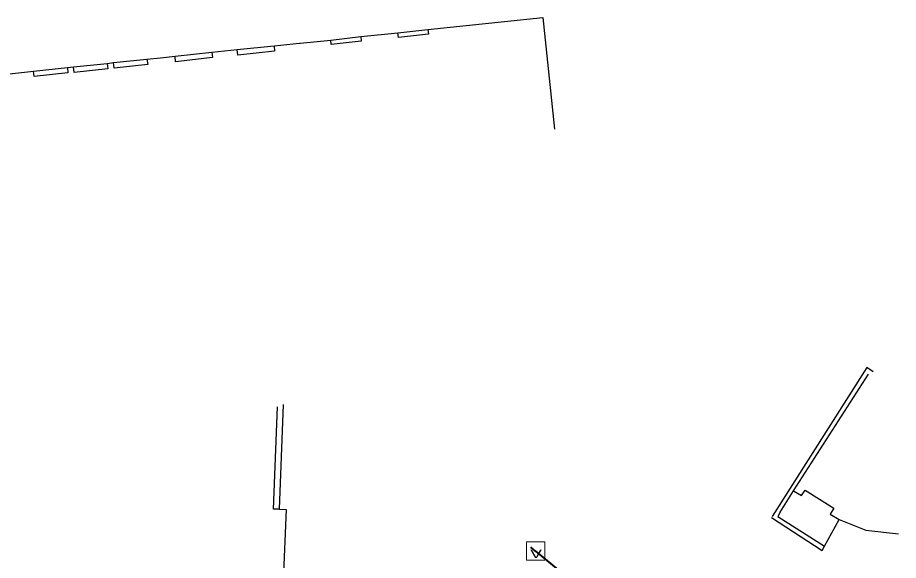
# Model space of a CAD drawing. Extents: x -968691 to -140888, y -1376050 to -879856.
# Drawn here: x -646162.3 to -646090.5, y -1062419.8 to -1062375.5 of the extents above; entities that cross this region are included whole.
import ezdxf
from ezdxf.enums import TextEntityAlignment as Align

# ---------------------------------------------------------------- set-up
doc = ezdxf.new("R2010")
doc.units = 0
doc.header["$LTSCALE"] = 4.8
for name, pattern in [('DOT_DASHED', [7.7, 5, -1.2, 0.3, -1.2]), ('DOTTED', [1.5, 0.3, -1.2]), ('LONG_DASH_SHORT_DASH', [9.9, 6, -1.2, 1.5, -1.2]), ('LONG_DASHED', [7.5, 6, -1.5]), ('MEDIUM_DASHED', [4.5, 3, -1.5])]:
    doc.linetypes.add(name, pattern=pattern)
doc.layers.add('1', color=7, linetype='Continuous', lineweight=13)

msp = doc.modelspace()

# ---------------------------------------------------------------- linework, layer by layer
at = {"layer": '1', "lineweight": 25}
for p, q in [((-646128.849, -1062376.51), (-646119.48, -1062375.54)), ((-646119.48, -1062375.54), (-646118.524, -1062384.643)), ((-646134.33, -1062377.082), (-646131.3, -1062376.773)), ((-646139.286, -1062377.629), (-646136.781, -1062377.371)), ((-646146.481, -1062378.37), (-646144.431, -1062378.147)), ((-646141.401, -1062377.844), (-646139.338, -1062377.634)), ((-646139.338, -1062377.634), (-646139.286, -1062377.629)), ((-646158.278, -1062379.612), (-646157.778, -1062379.553)), ((-646155.031, -1062379.284), (-646154.512, -1062379.211)), ((-646168.66, -1062380.73), (-646161.051, -1062379.915)), ((-646140.965, -1062415.659), (-646140.434, -1062415.68)), ((-646140.434, -1062415.68), (-646140.71, -1062422.658))]:
    msp.add_line(p, q, dxfattribs=at)
at = {"layer": '1', "linetype": 'MEDIUM_DASHED', "lineweight": 25}
for p, q in [((-646131.3, -1062376.773), (-646128.849, -1062376.51)), ((-646136.781, -1062377.371), (-646134.33, -1062377.082)), ((-646144.431, -1062378.147), (-646141.401, -1062377.844)), ((-646154.512, -1062379.211), (-646151.778, -1062378.929)), ((-646149.484, -1062378.699), (-646146.481, -1062378.37)), ((-646161.051, -1062379.915), (-646158.278, -1062379.612)), ((-646157.778, -1062379.553), (-646155.031, -1062379.284)), ((-646140.965, -1062415.659), (-646140.629, -1062407.118)), ((-646096.49, -1062418.681), (-646095.296, -1062416.504))]:
    msp.add_line(p, q, dxfattribs=at)
at = {"layer": '1', "linetype": 'DOT_DASHED', "lineweight": 25}
for p, q in [((-646099.019, -1062414.154), (-646092.902, -1062404.632)), ((-646141.461, -1062415.64), (-646141.123, -1062407.306)), ((-646100.113, -1062415.907), (-646099.019, -1062414.154)), ((-646140.965, -1062415.659), (-646141.461, -1062415.64))]:
    msp.add_line(p, q, dxfattribs=at)
at = {"layer": '1', "linetype": 'DOTTED', "lineweight": 40}
msp.add_line((-646120.07, -1062419.07), (-646120.456, -1062418.752), dxfattribs=at)
at = {"layer": '1'}
for q in [(-646120.456, -1062418.752), (-646115.17, -1062423.11)]:
    msp.add_line((-646120.07, -1062419.07), q, dxfattribs=at)
at = {"layer": '1', "linetype": 'LONG_DASHED', "lineweight": 40}
msp.add_line((-646120.07, -1062419.07), (-646115.17, -1062423.11), dxfattribs=at)
at = {"layer": '1', "linetype": 'DOT_DASHED', "lineweight": 25}
for points in [[(-646128.849, -1062376.51), (-646128.803, -1062376.878), (-646131.254, -1062377.161), (-646131.3, -1062376.773)], [(-646134.33, -1062377.082), (-646134.297, -1062377.45), (-646136.748, -1062377.726), (-646136.781, -1062377.371)], [(-646141.401, -1062377.844), (-646141.362, -1062378.291), (-646144.372, -1062378.613), (-646144.431, -1062378.147)], [(-646151.778, -1062378.929), (-646151.719, -1062379.369), (-646154.459, -1062379.671), (-646154.512, -1062379.211)], [(-646146.481, -1062378.37), (-646146.422, -1062378.804), (-646149.445, -1062379.146), (-646149.484, -1062378.699)], [(-646158.278, -1062379.612), (-646158.238, -1062380.053), (-646160.985, -1062380.355), (-646161.051, -1062379.915)], [(-646155.031, -1062379.284), (-646154.985, -1062379.711), (-646157.719, -1062380.007), (-646157.778, -1062379.553)], [(-646099.019, -1062414.154), (-646098.365, -1062414.549), (-646098.072, -1062414.105)], [(-646098.072, -1062414.105), (-646095.734, -1062415.577), (-646096.027, -1062416.073), (-646095.296, -1062416.504)]]:
    msp.add_lwpolyline(points, dxfattribs=at)
at = {"layer": '1', "lineweight": 25}
for points in [[(-646151.778, -1062378.929), (-646150.685, -1062378.819), (-646149.484, -1062378.699)], [(-646095.296, -1062416.504), (-646093.119, -1062417.373), (-646090.463, -1062417.665)]]:
    msp.add_lwpolyline(points, dxfattribs=at)
at = {"layer": '1', "linetype": 'MEDIUM_DASHED', "lineweight": 25}
msp.add_lwpolyline([(-646092.53, -1062404.437), (-646093.037, -1062404.102), (-646100.815, -1062416.341), (-646096.671, -1062419.012), (-646096.49, -1062418.681)], dxfattribs=at)
at = {"layer": '1', "linetype": 'LONG_DASH_SHORT_DASH', "lineweight": 25}
msp.add_lwpolyline([(-646100.113, -1062415.907), (-646100.3, -1062416.238), (-646096.49, -1062418.681)], dxfattribs=at)
at = {"layer": '1'}
msp.add_lwpolyline([(-646120.82, -1062419.82), (-646119.32, -1062419.82), (-646119.32, -1062418.32), (-646120.82, -1062418.32)], close=True, dxfattribs=at)

# ---------------------------------------------------------------- texts
at = {"layer": '1', "width": 1.55}
msp.add_text('V', height=0.7, dxfattribs=at).set_placement((-646120.031, -1062419.649), align=Align.CENTER)

doc.saveas('drawing.dxf')
